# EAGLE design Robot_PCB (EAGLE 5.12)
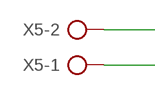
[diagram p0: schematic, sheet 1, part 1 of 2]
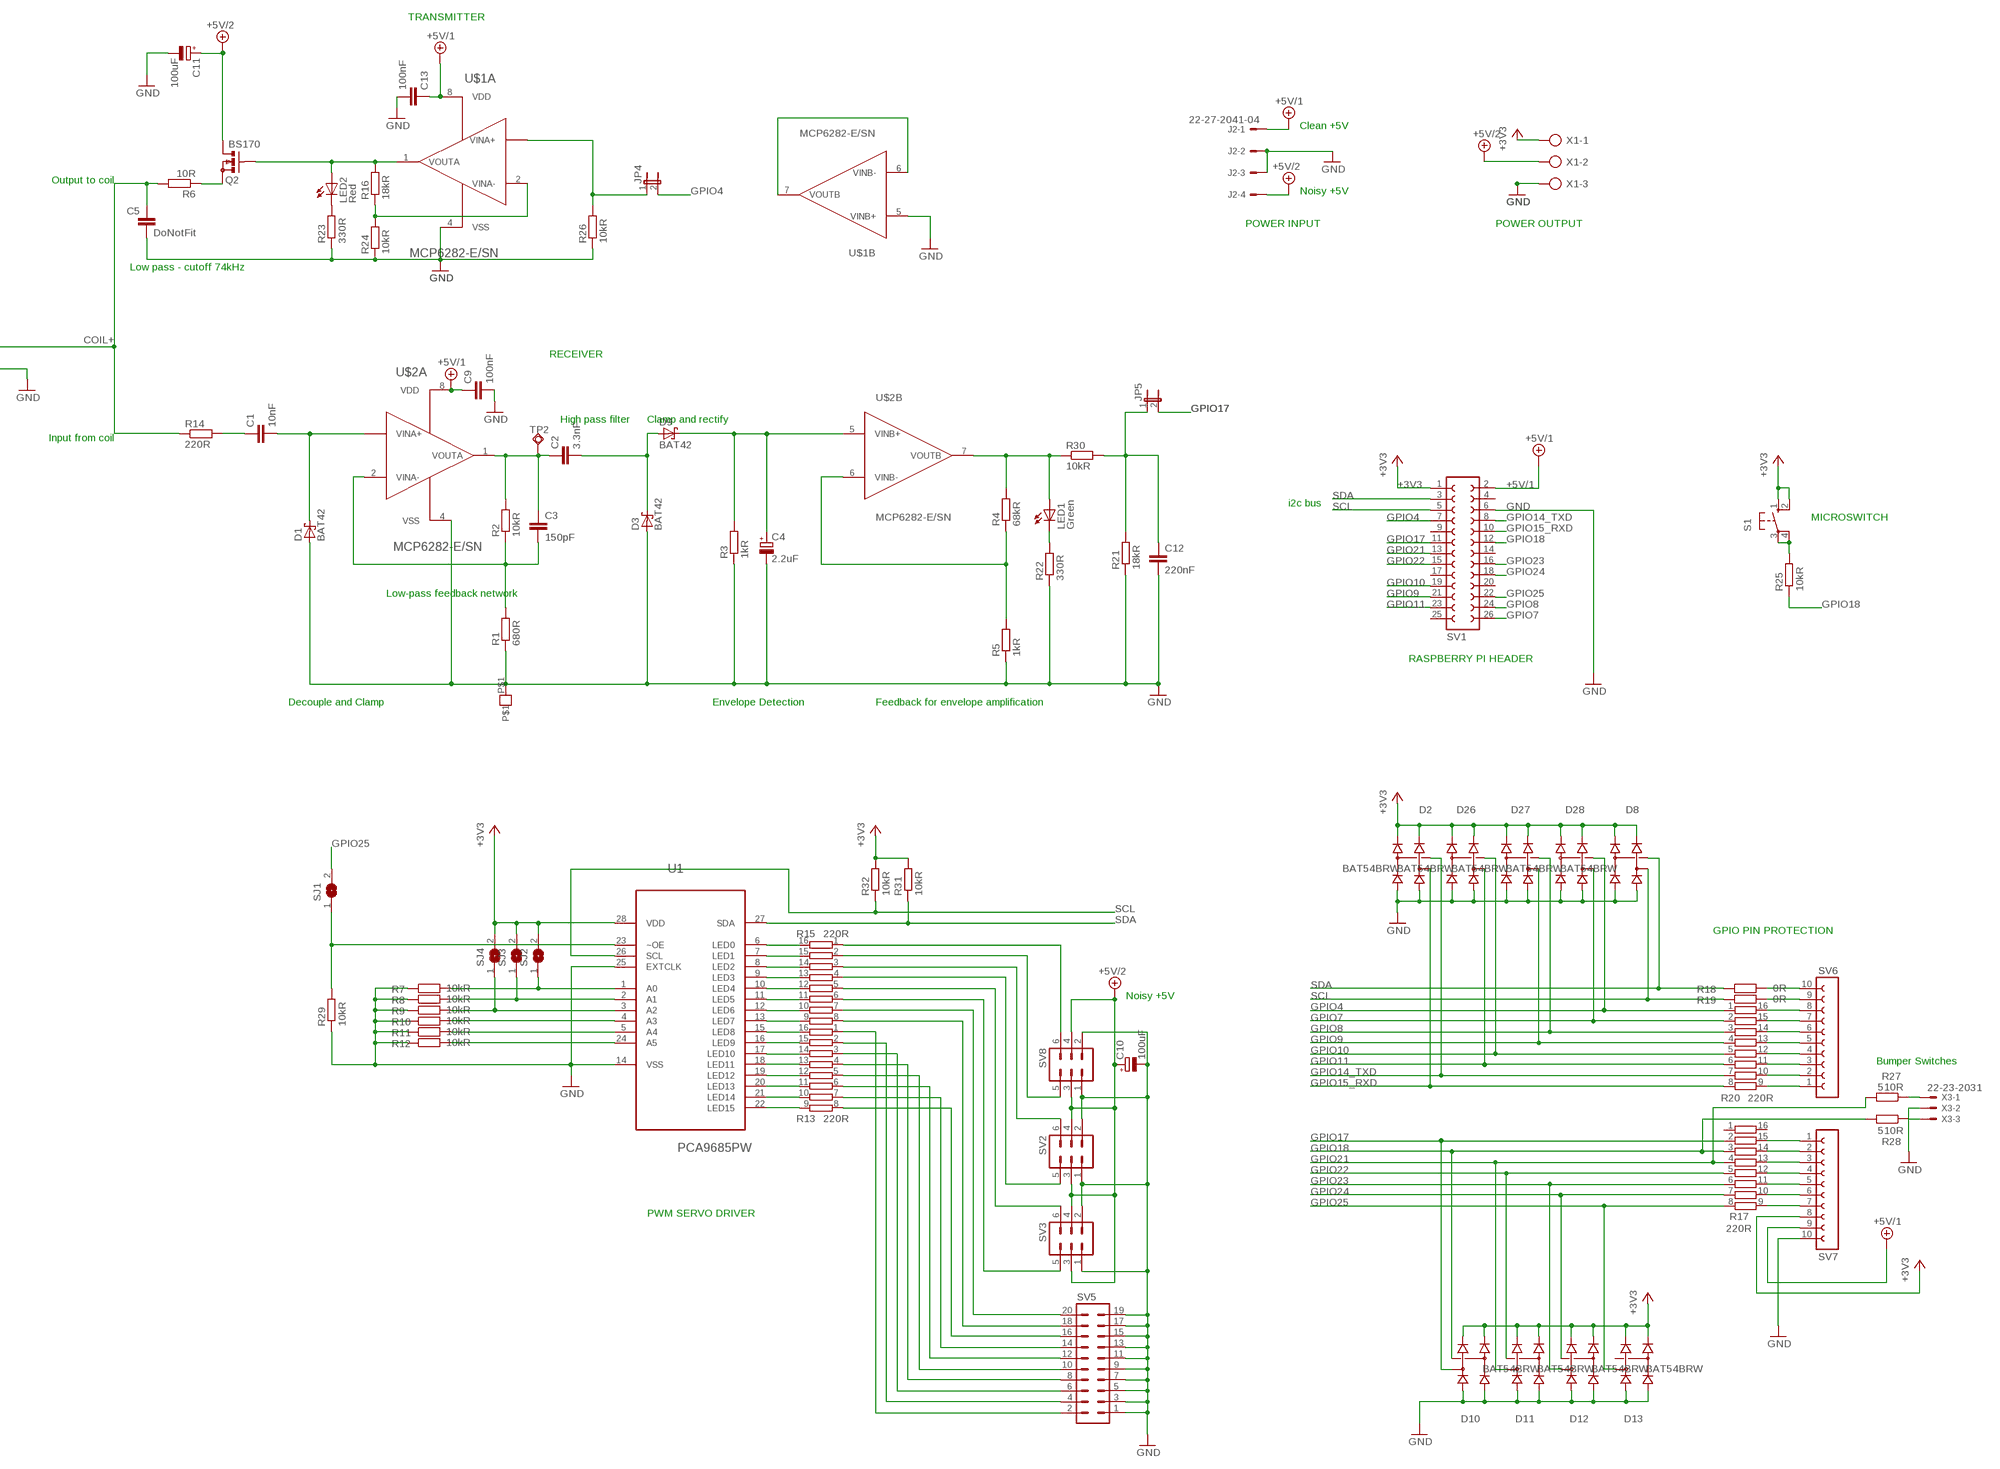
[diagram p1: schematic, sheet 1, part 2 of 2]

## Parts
C1  10nF  C-EUC0603  [C0603]
C2  3.3nF  C-EUC0603  [C0603]
C3  150pF  C-EUC0603  [C0603]
C4  2.2uF  CPOL-EUE2-5  [E2-5]
C5  DoNotFit  C-EU025-024X044  [C025-024X044]
C9  100nF  C-EUC0603  [C0603]
C10  100uF  CPOL-EUE2.5-6  [E2,5-6]
C11  100uF  CPOL-EUE2.5-6  [E2,5-6]
C12  220nF  C-EU025-024X044  [C025-024X044]
C13  100nF  C-EUC0603  [C0603]
D1  BAT42  [DO35-10]
D2  BAT54BRW  [SOT363]
D3  BAT42  [DO35-10]
D8  BAT54BRW  [SOT363]
D9  BAT42  [DO35-10]
D10  BAT54BRW  [SOT363]
D11  BAT54BRW  [SOT363]
D12  BAT54BRW  [SOT363]
D13  BAT54BRW  [SOT363]
D26  BAT54BRW  [SOT363]
D27  BAT54BRW  [SOT363]
D28  BAT54BRW  [SOT363]
J2  22-27-2041-04  [6410-04]
J5  TP  [TP_SMALL]
JP4  JP1E  [JP1]
JP5  JP1E  [JP1]
LED1  Green  LEDSML0805  [SML0805]
LED2  Red  LEDSML0805  [SML0805]
Q2  BS170  [SOT54E]
R1  680R  R-EU_R0603  [R0603]
R2  10kR  R-EU_R0603  [R0603]
R3  1kR  R-EU_R0603  [R0603]
R4  68kR  R-EU_R0603  [R0603]
R5  1kR  R-EU_R0603  [R0603]
R6  10R  R-EU_0207/10  [0207/10]
R7  10kR  R-EU_R0603  [R0603]
R8  10kR  R-EU_R0603  [R0603]
R9  10kR  R-EU_R0603  [R0603]
R10  10kR  R-EU_R0603  [R0603]
R11  10kR  R-EU_R0603  [R0603]
R12  10kR  R-EU_R0603  [R0603]
R13  220R  2NBS16-8  [SO16]
R14  220R  R-EU_R0603  [R0603]
R15  220R  2NBS16-8  [SO16]
R16  18kR  R-EU_R0603  [R0603]
R17  220R  4816P-T01  [4816P]
R18  0R  R-EU_R0603  [R0603]
R19  0R  R-EU_R0603  [R0603]
R20  220R  4816P-T01  [4816P]
R21  18kR  R-EU_R0603  [R0603]
R22  330R  R-EU_R0603  [R0603]
R23  330R  R-EU_R0603  [R0603]
R24  10kR  R-EU_R0603  [R0603]
R25  10kR  R-EU_R0603  [R0603]
R26  10kR  R-EU_R0603  [R0603]
R27  510R  R-EU_R0603  [R0603]
R28  510R  R-EU_R0603  [R0603]
R29  10kR  R-EU_R0603  [R0603]
R30  10kR  R-EU_R0603  [R0603]
R31  10kR  R-EU_R0603  [R0603]
R32  10kR  R-EU_R0603  [R0603]
S1  10-XX  [B3F-10XX]
SJ1  SJ  [SJ]
SJ2  SJ  [SJ]
SJ3  SJ  [SJ]
SJ4  SJ  [SJ]
SV1  FE13-2  [FE13-2]
SV2  MA03-2  [MA03-2]
SV3  MA03-2  [MA03-2]
SV5  MA10-2  [MA10-2]
SV6  FE10-1  [FE10]
SV7  FE10-1  [FE10]
SV8  MA03-2  [MA03-2]
TP2  TPSQTP16SQ  [TP16SQ]
U1  PCA9685PW  [SOP65P640X110-28N]
U$1  MCP6282-E/SN  [SOIC127P600X175-8N]
U$2  MCP6282-E/SN  [SOIC127P600X175-8N]
X1  AK500/3  [AK500/3]
X3  22-23-2031  [22-23-2031]
X5  AK500/2  [AK500/2]

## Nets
+3V3: D2.P$4(C2) D2.P$5(C1) D8.P$4(C2) D8.P$5(C1) D10.P$4(C2) D10.P$5(C1) D11.P$4(C2) D11.P$5(C1) D12.P$4(C2) D12.P$5(C1) D13.P$4(C2) D13.P$5(C1) D26.P$4(C2) D26.P$5(C1) D27.P$4(C2) D27.P$5(C1) D28.P$4(C2) D28.P$5(C1) R31.2 R32.2 S1.1(S) S1.2(S1) SJ2.2 SJ3.2 SJ4.2 SV1.1 SV7.8 U1.28(VDD) X1.1
+5V/1: C9.1 C13.1 J2.1 SV1.2 SV7.9 U$1.8(A:VDD) U$2.8(A:VDD)
+5V/2: C10.+ C11.+ J2.4 Q2.D SV2.3 SV2.4 SV3.3 SV3.4 SV8.3 SV8.4 X1.2
COIL+: C5.1 R6.2 R14.1 X5.2
GND: C4.- C5.2 C9.2 C10.- C11.- C12.2 C13.2 D1.A D2.P$1(A1) D2.P$2(A2) D3.A D8.P$1(A1) D8.P$2(A2) D10.P$1(A1) D10.P$2(A2) D11.P$1(A1) D11.P$2(A2) D12.P$1(A1) D12.P$2(A2) D13.P$1(A1) D13.P$2(A2) D26.P$1(A1) D26.P$2(A2) D27.P$1(A1) D27.P$2(A2) D28.P$1(A1) D28.P$2(A2) J2.2 J2.3 J5.P$1 R1.1 R3.1 R5.1 R7.1 R8.1 R9.1 R10.1 R11.1 R12.1 R21.1 R22.1 R23.1 R24.1 R26.1 R29.1 SV1.6 SV2.1 SV2.2 SV3.1 SV3.2 SV5.1 SV5.3 SV5.5 SV5.7 SV5.9 SV5.11 SV5.13 SV5.15 SV5.17 SV5.19 SV7.10 SV8.1 SV8.2 U1.14(VSS) U1.25(EXTCLK) U$1.4(A:VSS) U$1.5(B:VINB+) U$2.4(A:VSS) X1.3 X3.2 X5.1
GPIO4: D28.P$3(AC2) JP4.2 R20.1 SV1.7
GPIO7: D28.P$6(AC1) R20.2 SV1.26
GPIO8: D27.P$3(AC2) R20.3 SV1.24
GPIO9: D27.P$6(AC1) R20.4 SV1.21
GPIO10: D26.P$3(AC2) R20.5 SV1.19
GPIO11: D26.P$6(AC1) R20.6 SV1.23
GPIO14_TXD: D2.P$3(AC2) R20.7 SV1.8
GPIO15_RXD: D2.P$6(AC1) R20.8 SV1.10
GPIO17: D10.P$6(AC1) JP5.2 R17.2 SV1.11
GPIO18: D10.P$3(AC2) R17.3 R25.1 R28.2 SV1.12
GPIO21: D11.P$6(AC1) R17.4 R27.2 SV1.13
GPIO22: D11.P$3(AC2) R17.5 SV1.15
GPIO23: D12.P$6(AC1) R17.6 SV1.16
GPIO24: D12.P$3(AC2) R17.7 SV1.18
GPIO25: D13.P$6(AC1) R17.8 SJ1.2 SV1.22
N$1: R17.9 SV7.7
N$2: C1.2 D1.C U$2.3(A:VINA+)
N$3: Q2.S R6.1
N$5: C2.1 C3.1 R2.2 TP2.TP U$2.1(A:VOUTA)
N$6: LED1.C R22.2
N$7: C4.+ D9.C R3.2 U$2.5(B:VINB+)
N$8: R7.2 SJ2.1 U1.1(A0)
N$9: R4.1 R5.2 U$2.6(B:VINB-)
N$12: C3.2 R1.2 R2.1 U$2.2(A:VINA-)
N$13: R18.2 SV6.10
N$15: R19.2 SV6.9
N$16: R8.2 SJ3.1 U1.2(A1)
N$21: R15.16 U1.6(LED0)
N$22: R17.10 SV7.6
N$23: R9.2 SJ4.1 U1.3(A2)
N$24: R10.2 U1.4(A3)
N$25: R11.2 U1.5(A4)
N$26: R12.2 U1.24(A5)
N$29: R15.2 SV8.5
N$30: R15.1 SV8.6
N$31: C2.2 D3.C D9.A
N$32: R15.4 SV2.5
N$33: R15.5 SV3.6
N$34: R15.6 SV3.5
N$35: R15.15 U1.7(LED1)
N$36: R15.14 U1.8(LED2)
N$38: R15.13 U1.9(LED3)
N$39: R15.12 U1.10(LED4)
N$40: R15.11 U1.11(LED5)
N$41: R15.10 U1.12(LED6)
N$42: R15.9 U1.13(LED7)
N$43: R13.16 U1.15(LED8)
N$44: R13.15 U1.16(LED9)
N$45: R13.14 U1.17(LED10)
N$46: R13.13 U1.18(LED11)
N$47: R13.12 U1.19(LED12)
N$48: R13.11 U1.20(LED13)
N$49: R13.10 U1.21(LED14)
N$50: R13.9 U1.22(LED15)
N$51: R15.7 SV5.20
N$52: R15.8 SV5.18
N$53: R13.8 SV5.16
N$54: R13.7 SV5.14
N$55: R13.6 SV5.12
N$56: R13.5 SV5.10
N$57: R13.4 SV5.8
N$58: R13.3 SV5.6
N$59: R13.2 SV5.4
N$60: R13.1 SV5.2
N$61: C1.1 R14.2
N$62: JP4.1 R26.2 U$1.3(A:VINA+)
N$63: LED1.A R4.2 R30.1 U$2.7(B:VOUTB)
N$64: R17.11 SV7.5
N$65: R17.12 SV7.4
N$71: R17.13 SV7.3
N$72: R17.14 SV7.2
N$73: R17.15 SV7.1
N$75: LED2.A Q2.G R16.2 U$1.1(A:VOUTA)
N$78: R20.9 SV6.1
N$79: R16.1 R24.2 U$1.2(A:VINA-)
N$80: C12.1 JP5.1 R21.2 R30.2
N$82: R15.3 SV2.6
N$83: R20.10 SV6.2
N$85: R28.1 X3.3
N$92: R20.11 SV6.3
N$93: R20.12 SV6.4
N$94: R20.13 SV6.5
N$95: R20.14 SV6.6
N$96: R20.15 SV6.7
N$97: R20.16 SV6.8
N$98: R25.2 S1.3(P) S1.4(P1)
N$105: LED2.C R23.2
N$132: R27.1 X3.1
N$133: U$1.6(B:VINB-) U$1.7(B:VOUTB)
SCL: D8.P$6(AC1) R19.1 R32.1 SV1.5 U1.26(SCL)
SDA: D8.P$3(AC2) R18.1 R31.1 SV1.3 U1.27(SDA)
~ENAB_PCA9685PW: R29.2 SJ1.1 U1.23(~OE)
Unconnected: D13.P$3(AC2) R17.1 R17.16 SV1.4 SV1.9 SV1.14 SV1.17 SV1.20 SV1.25

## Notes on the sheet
- TRANSMITTER
- Clean +5V
- Output to coil
- Noisy +5V
- POWER INPUT | POWER OUTPUT
- Low pass - cutoff 74kHz
- RECEIVER
- High pass filter | Clamp and rectify
- Input from coil
- i2c bus
- MICROSWITCH
- Low-pass feedback network
- RASPBERRY PI HEADER
- Decouple and Clamp | Envelope Detection | Feedback for envelope amplification
- GPIO PIN PROTECTION
- Noisy +5V
- Bumper Switches
- PWM SERVO DRIVER

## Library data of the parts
C1-C3 C5 C9 C12 C13 = resistor:C-EU: CAPACITOR, European symbol
C4 C10 C11 = resistor:CPOL-EU: POLARIZED CAPACITOR, European symbol
D1 D3 D9 = diode:BAT42: DIODE
D2 D8 D10-D13 D26-D28 = dtg:BAT54BRW
J2 = con-molex:22-?-04: CONNECTOR wire to board 2.54 mm (.1 inch) pitch header; OC_FARNELL: unknown; OC_NEWARK: unknown
J5 = dtg:TP
JP4 JP5 = jumper:JP1E: JUMPER
LED1 LED2 = led:LED: LED
Q2 = transistor-small-signal:BS170: N-CHANNEL MOS FET
R1-R12 R14 R16 R18 R19 R21-R32 = resistor:R-EU_: RESISTOR, European symbol
R13 R15 = resistor-bourns:2NBS16-8: BOURNS RESISTOR NETWORK; OC_FARNELL: unknown; OC_NEWARK: unknown
R17 R20 = resistor-bourns:4816P-T01: BOURNS RESISTOR NETWORK; MF: BOURNS, INC.; MPN: 4816P-T01-684LF; OC_FARNELL: 9357483; OC_NEWARK: 33K0707
S1 = switch-omron:10-XX: OMRON SWITCH; MPN: B3F-1000; OC_FARNELL: 176432; OC_NEWARK: 36M3542
SJ1-SJ4 = jumper:SJ: SMD solder JUMPER
SV1 = con-lsta:FE13-2: FEMALE HEADER; OC_FARNELL: unknown; OC_NEWARK: unknown
SV2 SV3 SV8 = con-lstb:MA03-2: PIN HEADER; OC_FARNELL: unknown; OC_NEWARK: unknown
SV5 = con-lstb:MA10-2: PIN HEADER; OC_FARNELL: unknown; OC_NEWARK: unknown
SV6 SV7 = con-lsta:FE10-1: FEMALE HEADER; OC_FARNELL: unknown; OC_NEWARK: unknown
TP2 = testpad:TPSQ: Test pad
U1 = NXP_PCA9685PW:PCA9685PW: 16-channel, 12-bit PWM Fm+ I2C-bus LED controller; MPN: PCA9685PW; OC_FARNELL: 1854074; OC_NEWARK: 19T6398; PACKAGE: TSSOP-28; SUPPLIER: NXP
U$1 U$2 = MCP6282_mine:MCP6282-E/SN: Rail-to-Rail Op Amp; DESCRIPTION: OP AMP; MPN: MCP6282-E/SN; OC_FARNELL: 1439459; OC_NEWARK: 58M8972; PACKAGE: SOIC-8; SUPPLIER: Microchip
X1 = con-ptr500:AK500/3: CONNECTOR; OC_FARNELL: unknown; OC_NEWARK: unknown
X3 = con-molex:22-23-2031: .100" (2.54mm) Center Header - 3 Pin; MF: MOLEX; MPN: 22-23-2031; OC_FARNELL: 1462950; OC_NEWARK: 30C0862
X5 = con-ptr500:AK500/2: CONNECTOR; OC_FARNELL: unknown; OC_NEWARK: unknown

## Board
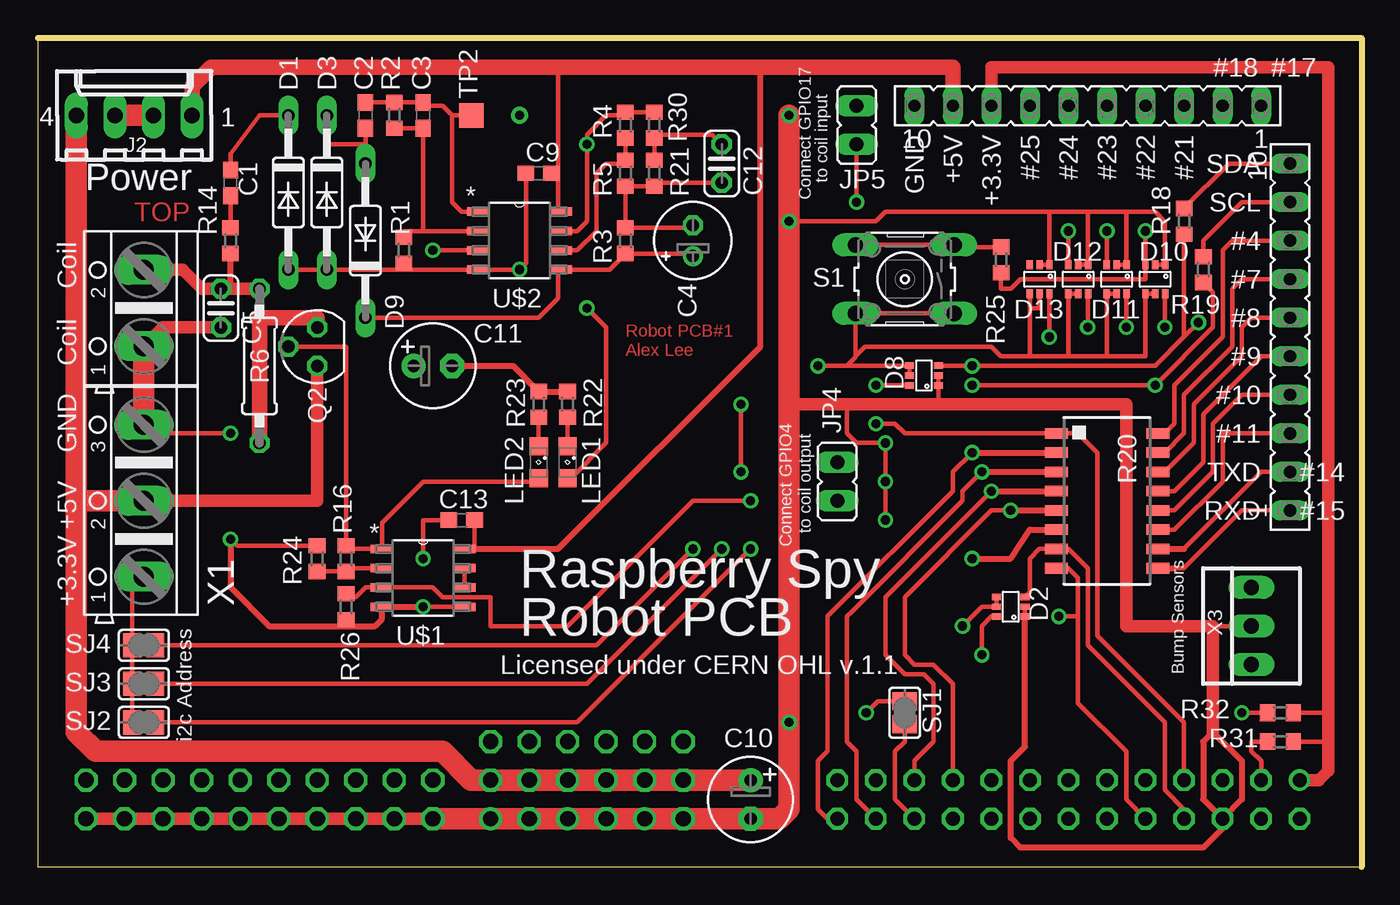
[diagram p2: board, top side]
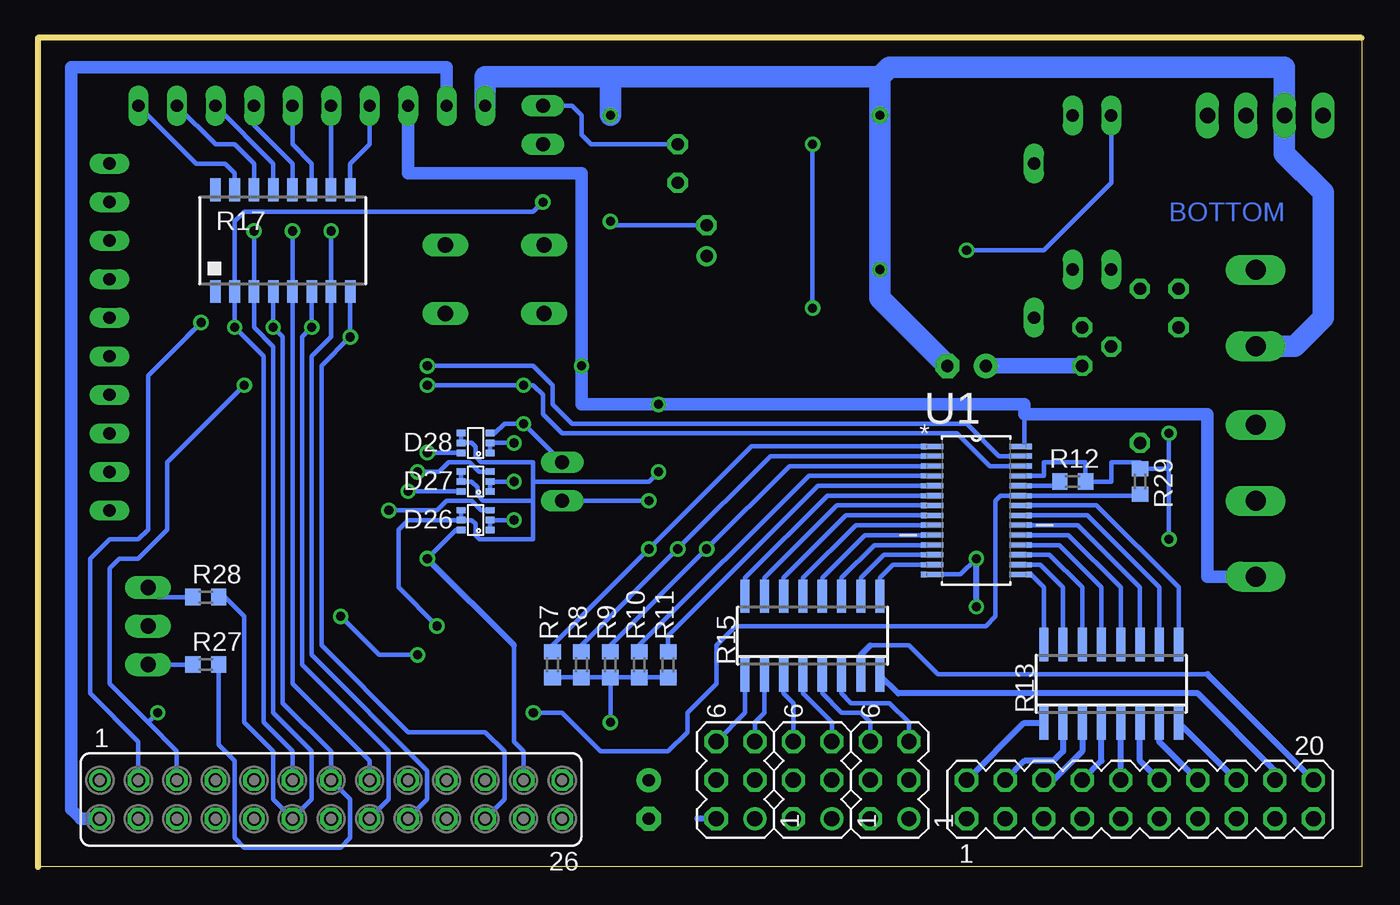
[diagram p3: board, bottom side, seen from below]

Size 87.27 x 54.63 mm. Coordinates in mm from the lower left corner, seen from the top.
Outline: 0,0 87.27,0 87.27,54.63 0,54.63 0,0
Copper layers (1*16): Top 0.035mm / dielectric 1.5mm / Bottom 0.035mm
Design rules "default *": minimum track width 10mil, minimum drill 23mil, track to track 8mil, track to pad 8mil, pad to pad 8mil, via to via 8mil, smd to smd 8mil, copper to edge 40mil, drill to drill 8mil, minimum pad ring 10mil, minimum via ring 8mil, stop-mask expansion 4mil, vias tented up to drill 0mil, thermal gap 15mil

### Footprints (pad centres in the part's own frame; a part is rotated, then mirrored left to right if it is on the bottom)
C0603 = smd 1.1 x 1: 1 -0.85,0; 2 0.85,0
E2-5 = drill 0.813 pad 1.27 round: + -1.016,0 | drill 0.813 pad 1.27 octagon: - 1.016,0
C025-024X044 = drill 0.813 octagon: 1 -1.27,0; 2 1.27,0
E2,5-6 = drill 0.813 pad 1.6 round: + -1.27,0 | drill 0.813 pad 1.6 octagon: - 1.27,0
DO35-10 = drill 0.813 long: A 5.08,0; C -5.08,0
SOT363 = smd 0.42 x 0.6: P$1 -0.65,-0.95; P$2 0,-0.95; P$3 0.65,-0.95; P$4 0.65,0.95; P$5 0,0.95; P$6 -0.65,0.95
6410-04 = drill 1.016 long: 1 3.81,0; 2 1.27,0; 3 -1.27,0; 4 -3.81,0
TP_SMALL = drill 0.6 pad 0.813 round: P$1 0,0
JP1 = drill 0.914 long: 1 0,-1.27; 2 0,1.27
SML0805 = smd 1.2 x 1.2: A 1.05,0; C -1.05,0
SOT54E = drill 0.813 octagon: D -1.27,0; G 0,1.905; S 1.27,0
R0603 = smd 1 x 1.1: 1 -0.85,0; 2 0.85,0
0207/10 = drill 0.813 octagon: 1 -5.08,0; 2 5.08,0
SO16 = smd 0.6 x 2.2: 1 -4.445,-2.6; 2 -3.175,-2.6; 3 -1.905,-2.6; 4 -0.635,-2.6; 5 0.635,-2.6; 6 1.905,-2.6; 7 3.175,-2.6; 8 4.445,-2.6; 9 4.445,2.6; 10 3.175,2.6; 11 1.905,2.6; 12 0.635,2.6; 13 -0.635,2.6; 14 -1.905,2.6; 15 -3.175,2.6; 16 -4.445,2.6
4816P = smd 0.7 x 1.5: 1 -4.445,-3.346; 2 -3.175,-3.346; 3 -1.905,-3.346; 4 -0.635,-3.346; 5 0.635,-3.346; 6 1.905,-3.346; 7 3.175,-3.346; 8 4.445,-3.346; 9 4.445,3.346; 10 3.175,3.346; 11 1.905,3.346; 12 0.635,3.346; 13 -0.635,3.346; 14 -1.905,3.346; 15 -3.175,3.346; 16 -4.445,3.346
B3F-10XX = drill 1.016 long: 1 -3.251,2.261; 2 3.251,2.261; 3 -3.251,-2.261; 4 3.251,-2.261
SJ = smd 1.168 x 1.6: 1 -0.762,0; 2 0.762,0
FE13-2 = drill 0.914 round: 1 -15.24,1.27 | drill 0.914 octagon: 2 -15.24,-1.27; 3 -12.7,1.27; 4 -12.7,-1.27; 5 -10.16,1.27; 6 -10.16,-1.27; 7 -7.62,1.27; 8 -7.62,-1.27; 9 -5.08,1.27; 10 -5.08,-1.27; 11 -2.54,1.27; 12 -2.54,-1.27; 13 0,1.27; 14 0,-1.27; 15 2.54,1.27; 16 2.54,-1.27; 17 5.08,1.27; 18 5.08,-1.27; 19 7.62,1.27; 20 7.62,-1.27; 21 10.16,1.27; 22 10.16,-1.27; 23 12.7,1.27; 24 12.7,-1.27; 25 15.24,1.27; 26 15.24,-1.27
MA03-2 = drill 1.016 round: 1 -2.54,-1.27 | drill 1.016 octagon: 2 -2.54,1.27; 3 0,-1.27; 4 0,1.27; 5 2.54,-1.27; 6 2.54,1.27
MA10-2 = drill 1.016 octagon: 1 -11.43,-1.27; 2 -11.43,1.27; 3 -8.89,-1.27; 4 -8.89,1.27; 5 -6.35,-1.27; 6 -6.35,1.27; 7 -3.81,-1.27; 8 -3.81,1.27; 9 -1.27,-1.27; 10 -1.27,1.27; 11 1.27,-1.27; 12 1.27,1.27; 13 3.81,-1.27; 14 3.81,1.27; 15 6.35,-1.27; 16 6.35,1.27; 17 8.89,-1.27; 18 8.89,1.27; 19 11.43,-1.27; 20 11.43,1.27
FE10 = drill 0.813 long: 1 -11.43,0; 2 -8.89,0; 3 -6.35,0; 4 -3.81,0; 5 -1.27,0; 6 1.27,0; 7 3.81,0; 8 6.35,0; 9 8.89,0; 10 11.43,0
TP16SQ = smd 1.6 x 1.6: TP 0,0
SOP65P640X110-28N = smd 1.473 x 0.356: 1 -2.921,4.216; 2 -2.921,3.581; 3 -2.921,2.921; 4 -2.921,2.286; 5 -2.921,1.626; 6 -2.921,0.965; 7 -2.921,0.33; 8 -2.921,-0.33; 9 -2.921,-0.965; 10 -2.921,-1.626; 11 -2.921,-2.286; 12 -2.921,-2.921; 13 -2.921,-3.581; 14 -2.921,-4.216; 15 2.921,-4.216; 16 2.921,-3.581; 17 2.921,-2.921; 18 2.921,-2.286; 19 2.921,-1.626; 20 2.921,-0.965; 21 2.921,-0.33; 22 2.921,0.33; 23 2.921,0.965; 24 2.921,1.626; 25 2.921,2.286; 26 2.921,2.921; 27 2.921,3.581; 28 2.921,4.216
SOIC127P600X175-8N = smd 1.473 x 0.559: 1 -2.718,1.905; 2 -2.718,0.635; 3 -2.718,-0.635; 4 -2.718,-1.905; 5 2.718,-1.905; 6 2.718,-0.635; 7 2.718,0.635; 8 2.718,1.905
AK500/3 = drill 1.321 long: 1 -5.004,0; 2 0,0; 3 5.004,0
22-23-2031 = drill 1 long: 1 -2.54,0; 2 0,0; 3 2.54,0
AK500/2 = drill 1.321 long: 1 -2.515,0; 2 2.515,0

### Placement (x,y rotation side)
C1  12.7,45.09 90 top
C2  21.59,49.53 270 top
C3  25.4,49.53 270 top
C4  43.18,41.27 90 top
C5  12.06,36.83 270 top
C9  33.02,45.72 180 top
C10  46.99,4.45 270 top
C11  26.04,33.02 0 top
C12  45.09,46.35 270 top
C13  27.94,22.86 180 top
D1  16.51,44.45 270 top
D2  64.14,17.14 90 top
D3  19.05,44.45 270 top
D8  58.42,32.38 90 top
D9  21.59,41.27 90 top
D10  73.66,38.73 180 top
D11  71.12,38.73 180 top
D12  68.58,38.73 180 top
D13  66.04,38.73 180 top
D26  58.42,22.86 90 bottom
D27  58.42,25.4 90 bottom
D28  58.42,27.94 90 bottom
J2  6.35,49.53 0 top
J5  31.75,49.53 0 top
JP4  52.7,25.4 0 top
JP5  53.98,48.9 180 top
LED1  34.92,26.67 270 top
LED2  33.02,26.67 270 top
Q2  18.41,34.29 90 top
R1  24.13,40.64 90 top
R2  23.5,49.53 90 top
R3  38.73,41.27 270 top
R4  38.73,48.9 90 top
R5  38.73,45.72 90 top
R6  14.61,33.02 90 top
R7  53.34,13.34 90 bottom
R8  51.44,13.34 90 bottom
R9  49.53,13.34 90 bottom
R10  47.62,13.34 90 bottom
R11  45.72,13.34 90 bottom
R12  19.05,25.4 180 bottom
R13  16.51,12.06 0 bottom
R14  12.7,41.27 90 top
R15  36.2,15.24 0 bottom
R16  20.32,20.32 90 top
R17  71.12,41.27 0 bottom
R18  75.56,42.55 90 top
R19  76.83,39.37 90 top
R20  70.48,24.13 270 top
R21  40.64,45.72 90 top
R22  34.92,30.48 270 top
R23  33.02,30.48 270 top
R24  18.41,20.32 270 top
R25  63.5,40.01 90 top
R26  20.32,17.14 90 top
R27  76.2,13.34 0 bottom
R28  76.2,17.78 0 bottom
R29  14.61,25.4 270 bottom
R30  40.64,48.9 270 top
R31  81.92,8.26 0 top
R32  81.92,10.16 0 top
S1  57.15,38.73 180 top
SJ1  57.15,10.16 270 top
SJ2  6.99,9.53 180 top
SJ3  6.99,12.06 180 top
SJ4  6.99,14.61 180 top
SV1  67.94,4.45 0 bottom
SV2  36.2,5.71 90 bottom
SV3  31.11,5.71 90 bottom
SV5  14.61,4.45 0 bottom
SV6  82.55,34.92 90 top
SV7  69.22,50.16 180 top
SV8  41.27,5.71 90 bottom
TP2  28.57,49.53 0 top
U1  25.4,23.5 0 bottom
U$1  25.4,19.05 0 top
U$2  31.75,41.27 0 top
X1  6.99,24.13 90 top
X3  80.01,15.88 90 top
X5  6.99,36.83 90 top

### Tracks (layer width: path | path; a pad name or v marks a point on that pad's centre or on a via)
+3V3  (via drill 0.6)
  Top 0.305: SJ2.2 SJ3.2 SJ4.2 6.22,19 6.1,19.13 X1.1 | S1.1 S1.2 53.9,33.66 | 53.9,33.66 53.9,33.58 53.35,33.03 | v51.44,33.02 53.34,33.02 53.35,33.03 | 67.94,33.66 67.93,33.67 D12.P$4 D12.P$5 | 65.41,33.66 63.5,33.66 62.87,34.29 54.53,34.29 53.9,33.66 | 65.41,33.66 67.94,33.66 | 65.39,36.83 65.39,33.67 65.41,33.66 | 65.39,36.83 D13.P$4 | 70.48,33.66 70.47,33.67 D11.P$4 D11.P$5 | 67.94,33.66 70.48,33.66 | 70.48,33.66 73.03,33.66 73.01,33.67 D10.P$4 D10.P$5 | D8.P$5 D8.P$4 53.35,33.03 | v46.35,30.48 v46.35,26.04 | v60.96,15.88 62.23,17.14 D2.P$5 D2.P$4 | D13.P$5 66.04,36.83 65.39,36.83 | 85.09,8.26 R31.2 | 85.09,10.16 R32.2
  Top 0.813: SV7.8 62.87,52.7 85.09,52.7 85.09,10.16 85.09,8.26 85.09,6.35 84.45,5.71 SV1.1
  Bottom 0.305: U1.28 22.23,27.71 22.23,29.84 | D27.P$4 D27.P$5 58.67,25.4 58.29,25.02 58.29,24.51 57.91,24.13 54.61,24.13 | D28.P$5 59.05,27.94 | D26.P$5 D26.P$4 59.37,23.18 | D28.P$5 D28.P$4 | 54.61,24.13 54.61,21.59 58.17,21.59 58.42,21.84 58.42,22.61 58.67,22.86 D26.P$5 | 54.61,25.4 54.61,24.13 | 54.61,25.4 54.61,26.67 58.04,26.67 58.42,27.05 58.42,27.69 58.67,27.94 D28.P$5 | v46.35,26.04 46.99,25.4 54.61,25.4 | v60.96,15.88 63.5,18.41 63.5,22.23 62.87,22.86 D26.P$5
  Bottom 0.813: X1.1 10.16,19.13 10.16,29.84 22.23,29.84 22.23,30.48 v46.35,30.48 51.44,30.48 v51.44,33.02 51.44,45.72 62.87,45.72 SV7.8
+5V/1
  Top 0.305: U$2.8 34.29,43.18 34.29,45.72 | 34.29,52.7 34.29,45.72 | 34.29,45.72 C9.1 | C13.1 28.79,21.17 28.57,20.95
  Top 0.406: U$1.8 28.57,20.95 34.29,20.95 47.62,34.29 47.62,52.7
  Top 1.016: SV7.9 60.33,52.7 47.62,52.7 34.29,52.7 11.43,52.7 10.16,51.44 J2.1
  Bottom 0.813: SV7.9 60.33,52.7 85.09,52.7 85.09,3.81 84.45,3.17 SV1.2
+5V/2
  Top 0.813: X1.2 18.41,24.13 Q2.D
  Top 1.422: 2.54,24.13 X1.2 | 2.54,24.13 2.54,8.89 3.81,7.62 26.67,7.62 28.57,5.71 SV3.3 SV3.4 SV2.3 SV2.4 SV8.3 SV8.4 C10.+ | 2.54,24.13 J2.4
  Bottom 1.016: Q2.D C11.+
COIL+
  Top 0.406: 12.7,38.1 R14.1
  Top 0.813: R6.2 14.82,38.1 | R6.2 14.39,37.88 | X5.2 9.55,39.34 10.79,38.1 C5.1 12.7,38.1 R6.2
GND  (via drill 0.6)
  Top 0.305: D1.A D3.A 24.13,39.37 | 24.13,39.37 R1.1 | 24.13,39.37 U$2.4 v31.75,39.37 32.17,39.79 C9.2 | C12.2 40.85,45.09 R21.1 R5.1 R3.1 43.01,42.12 C4.- | 49.53,34.29 49.15,34.67 | v12.7,28.57 5.71,28.57 X1.3 | 49.53,27.3 49.53,27.52 | R24.1 13.12,21.17 v12.7,21.59 | C13.2 25.4,22.86 v25.4,20.32 | 77.47,15.88 X3.2 | 66.67,43.18 55.88,43.18 55.24,42.55 v49.53,42.55 | 66.67,43.18 69.22,43.18 | 69.22,43.18 71.75,43.18 | 71.75,43.18 73.66,43.18 74.31,42.53 D10.P$1 D10.P$2 | 71.75,43.18 71.77,43.16 D11.P$1 D11.P$2 | 69.22,43.18 69.23,43.16 D12.P$1 D12.P$2 | 66.67,43.18 66.69,43.16 D13.P$1 D13.P$2 | 59.69,30.48 59.37,30.8 D8.P$1 D8.P$2 | v55.88,22.86 v55.88,25.4 v55.88,27.94 53.98,27.94 53.34,28.57 53.34,30.48 | D2.P$1 D2.P$2 | v25.4,17.14 U$1.5
  Top 0.406: v12.7,21.59 12.7,18.41 15.24,15.88 20.32,15.88 | 20.32,15.88 22.23,15.88 22.68,16.33 U$1.4 v25.4,17.14 | 20.32,15.88 R26.1 | C11.- 31.33,33.02 R23.1 R22.1 | SV1.6 76.83,4.45 76.83,8.26 77.47,8.89 79.38,6.99 79.38,4.45 SV1.6 | D2.P$1 65.08,7.93 64.14,6.99 64.14,1.91 64.77,1.27 76.83,1.27 78.11,2.54 SV1.6
  Top 0.813: 49.53,30.48 53.34,30.48 59.69,30.48 71.75,30.48 71.75,15.88 77.47,15.88 77.47,8.89 | SV5.1 SV5.3 SV5.5 SV5.7 SV5.9 | SV5.9 15.24,3.17 | SV5.9 SV5.11 SV5.13 SV5.15 SV5.17 SV5.19 | C5.2 8.23,35.56 X5.1
  Top 1.422: J2.3 J2.2 | v49.53,49.53 v49.53,42.55 49.53,34.29 49.53,30.48 49.53,27.3 v49.53,9.53 49.53,3.81 48.9,3.17 C10.- SV8.2 SV8.1 SV2.2 SV2.1 SV3.2 SV3.1 SV5.1 | X5.1 X1.3
  Bottom 0.305: R9.1 R8.1 R7.1 | R9.1 R10.1 R11.1 | U1.25 20.95,25.78 20.95,26.67 18.2,26.67 R12.1 16.51,25.4 16.51,26.67 14.61,26.67 R29.1 12.7,26.25 | v12.7,28.57 12.7,26.25 | v49.53,9.53 R9.1 | 12.7,26.25 v12.7,21.59 | C4.- 49.28,42.29 v49.53,42.55 | D26.P$1 D26.P$2 v55.88,22.86 | D27.P$1 D27.P$2 v55.88,25.4 | D28.P$1 D28.P$2 v55.88,27.94 | U1.14 26.44,19.28 v25.4,20.32
  Bottom 0.406: SV8.2 43.81,3.17 | v25.4,17.14 v25.4,20.32
  Bottom 1.422: 49.53,52.07 31.75,52.07 | 49.53,52.07 57.78,52.07 SV7.10 | 31.75,52.07 J5.P$1 v31.75,39.37 31.75,37.47 C11.- | v49.53,49.53 49.53,52.07 | 31.75,52.07 31.11,52.7 5.08,52.7 J2.3 5.08,46.99 2.54,44.45 2.54,36.2 4.42,34.31 X5.1
GPIO4  (via drill 0.6)
  Top 0.305: v55.24,29.21 56.52,29.21 57.15,28.57 R20.1 68.58,28.57 69.85,27.3 69.85,15.24 75.56,9.53 SV1.7
  Bottom 0.305: D28.P$3 57.45,28.57 57.15,28.57 56.52,29.21 v55.24,29.21 JP4.2
GPIO7  (via drill 0.6)
  Top 0.305: v61.59,27.3 60.33,26.04 60.33,24.77 52.07,16.51 52.07,7.62 51.44,6.99 51.44,3.81 52.07,3.17 SV1.26
  Top 0.406: v61.59,27.3 R20.2
  Bottom 0.305: D28.P$6 v61.58,27.29 v61.59,27.3
GPIO8  (via drill 0.6)
  Top 0.305: v62.23,26.04 60.96,24.77 60.96,24.13 53.66,16.83 53.34,16.51 53.34,8.26 53.98,7.62 53.98,4.45 SV1.24
  Top 0.406: v62.23,26.04 R20.3
  Bottom 0.305: D27.P$3 58.18,26.05 58.8,26.67 60.2,26.67 60.83,26.04 v62.23,26.04
GPIO9  (via drill 0.6)
  Top 0.305: v62.87,24.77 55.88,17.78 55.88,13.97 57.15,12.7 58.42,12.7 59.05,12.06 59.05,8.26 57.78,6.99 SV1.21
  Top 0.406: v62.87,24.77 R20.4
  Bottom 0.305: D27.P$6 62.85,24.75 v62.87,24.77
GPIO10  (via drill 0.6)
  Top 0.305: v64.14,23.5 62.87,23.5 57.15,17.78 57.15,13.97 57.78,13.34 59.05,13.34 60.33,12.06 SV1.19
  Top 0.406: v64.14,23.5 R20.5
  Bottom 0.305: D26.P$3 58.05,23.51 58.67,24.13 60.33,24.13 60.96,23.5 v64.14,23.5
GPIO11  (via drill 0.6)
  Top 0.406: v61.59,20.32 64.14,20.32 65.41,22.23 R20.6
  Bottom 0.305: D26.P$6 59.7,22.21 v61.59,20.32 | 55.88,14.61 55.88,8.26 55.24,7.62 SV1.23
  Bottom 0.406: 55.88,14.61 v61.59,20.32
GPIO14_TXD
  Top 0.305: D2.P$3 65.41,18.11 65.41,20.32 66.04,20.95 R20.7 67.94,20.95 69.22,19.68 69.22,14.61 74.3,9.53 74.3,5.08 75.56,3.81 SV1.8
GPIO15_RXD  (via drill 0.6)
  Top 0.305: R20.8 67.94,19.68 68.58,19.05 68.58,16.51 | 68.58,16.51 68.58,10.79 71.75,7.62 71.75,4.45 SV1.10 | D2.P$6 63.48,16.5 63.5,16.51 62.87,16.51 62.23,15.88 v62.23,13.97 | 68.58,16.51 v67.31,16.51
  Bottom 0.305: v62.23,13.97 64.77,13.97 v67.31,16.51
GPIO17  (via drill 0.6)
  Top 0.305: v53.98,43.81 JP5.2 | 74.3,37.47 74.3,37.77 D10.P$6 74.31,37.48 74.3,37.47 | v74.3,35.56 74.3,37.47
  Bottom 0.305: v53.98,43.81 54.61,43.18 73.66,43.18 74.3,42.55 R17.2 v74.3,35.56 72.39,33.66 72.39,9.53 70.48,7.62 SV1.11
GPIO18  (via drill 0.6)
  Top 0.305: v73.03,41.91 73.03,40.97 D10.P$3 73.03,39.67 73.03,38.73 64.77,38.73 64.14,38.1 63.5,38.1 R25.1
  Bottom 0.305: v73.03,41.91 R17.3 73.03,35.56 71.75,34.29 71.75,10.16 69.22,7.62 69.22,4.45 SV1.12 71.75,4.45 71.75,7.62 73.66,9.53 73.66,16.51 74.93,17.78 R28.2
GPIO21  (via drill 0.6)
  Top 0.305: D11.P$6 71.75,37.13 v71.75,35.56
  Bottom 0.305: R17.4 v71.75,35.56 71.12,34.92 71.12,10.79 67.94,7.62 SV1.13 66.67,4.45 66.67,1.91 67.31,1.27 73.66,1.27 74.3,1.91 74.3,6.99 75.35,8.04 R27.2
GPIO22  (via drill 0.6)
  Top 0.305: D11.P$3 70.47,41.9 v70.48,41.91
  Bottom 0.305: v70.48,41.91 R17.5 70.48,12.06 65.41,6.99 SV1.15
GPIO23  (via drill 0.6)
  Top 0.305: v69.22,35.56 69.22,37.13 D12.P$6
  Bottom 0.305: R17.6 v69.22,35.56 69.85,34.92 69.85,13.34 64.14,7.62 64.14,4.45 SV1.16
GPIO24  (via drill 0.6)
  Top 0.305: D12.P$3 67.93,41.9 v67.94,41.91
  Bottom 0.305: v67.94,41.91 R17.7 67.94,34.92 69.22,33.66 69.22,13.97 61.59,6.35 61.59,4.45 SV1.18
GPIO25  (via drill 0.6)
  Top 0.305: v66.67,34.92 66.67,36.5 D13.P$6 | SJ1.2 57.15,8.26 56.52,7.62 56.52,4.45 SV1.22
  Bottom 0.305: R17.8 v66.67,34.92 68.58,33.02 68.58,14.61 62.87,8.89 57.78,8.89 56.52,7.62 56.52,4.45 SV1.22
N$1
  Bottom 0.305: R17.9 66.67,46.35 65.41,47.62 SV7.7
N$2  (via drill 0.6)
  Top 0.305: v26.04,40.64 U$2.3 | C1.2 12.7,46.99 14.61,49.53 D1.C
  Bottom 0.305: v26.04,40.64 20.95,40.64 16.51,45.09 D1.C
N$3
  Top 1.016: R6.1 14.61,36.2 18.41,36.2 Q2.S
N$5
  Top 0.305: C2.1 R2.2 C3.1 25.4,50.16 26.67,50.16 27.3,49.53 | 27.3,49.53 27.3,43.81 27.94,43.18 U$2.1 | 27.3,49.53 TP2.TP
N$6
  Top 0.305: LED1.C R22.2
N$7
  Top 0.305: D9.C 33.02,36.2 34.29,37.47 34.29,39.19 U$2.5 37.68,39.37 R3.2 43.01,40.42 C4.+
N$8  (via drill 0.6)
  Top 0.305: SJ2.1 35.56,9.53 v46.99,20.95
  Bottom 0.305: U1.1 40.23,27.71 v46.99,20.95 53.34,14.61 R7.2
N$9
  Top 0.305: R4.1 R5.2 38.52,46.35 37.47,46.35 36.83,45.72 36.83,41.91 35.56,40.64 U$2.6
N$12
  Top 0.305: 25.4,41.91 C3.2 R2.1 | 25.4,41.91 U$2.2 | R1.2 24.13,41.91 25.4,41.91
N$13
  Top 0.305: SV6.10 78.53,46.35 R18.2
N$15
  Top 0.305: SV6.9 79.38,43.81 76.83,41.27 R19.2
N$16  (via drill 0.6)
  Top 0.305: SJ3.1 36.2,12.06 v45.09,20.95
  Bottom 0.305: U1.2 38.96,27.08 v45.09,20.95 51.44,14.61 R8.2
N$21
  Bottom 0.305: U1.6 35.23,24.46 40.64,19.05 R15.16
N$22
  Bottom 0.305: R17.10 SV7.6
N$23  (via drill 0.6)
  Top 0.305: SJ4.1 36.83,14.61 v43.18,20.95
  Bottom 0.305: U1.3 37.72,26.42 v43.18,20.95 49.53,14.61 R9.2
N$24
  Bottom 0.305: U1.4 36.45,25.78 47.62,14.61 R10.2
N$25
  Bottom 0.305: U1.5 35.84,25.12 45.72,15.24 R11.2
N$26
  Bottom 0.305: U1.24 20.18,25.12 R12.2
N$29
  Bottom 0.305: R15.2 39.37,10.16 40.01,9.53 SV8.5
N$30
  Bottom 0.305: R15.1 40.64,10.16 SV8.6
N$31
  Top 0.305: 21.59,47.62 D9.A | 21.59,47.62 C2.2 | 21.59,47.62 19.05,47.62 D3.C
N$32
  Bottom 0.305: R15.4 36.83,11.43 34.92,9.53 SV2.5
N$33
  Bottom 0.305: SV3.6 32.38,9.53 33.02,10.16 34.29,10.16 35.56,11.43 R15.5
N$34
  Bottom 0.305: R15.6 34.29,11.43 33.66,10.79 31.11,10.79 29.84,9.53 SV3.5
N$35
  Bottom 0.305: U1.7 34.59,23.82 39.37,19.05 R15.15
N$36
  Bottom 0.305: U1.8 33.98,23.16 38.1,19.05 R15.14
N$38
  Bottom 0.305: U1.9 33.35,22.53 36.83,19.05 R15.13
N$39
  Bottom 0.305: U1.10 32.74,21.87 35.56,19.05 R15.12
N$40
  Bottom 0.305: U1.11 32.13,21.21 34.29,19.05 R15.11
N$41
  Bottom 0.305: U1.12 31.5,20.57 33.02,19.05 R15.10
N$42
  Bottom 0.305: 31.75,17.78 31.69,17.78 R15.9 31.75,19.05 30.89,19.91 U1.13
N$43
  Bottom 0.305: U1.15 21.82,19.28 20.95,18.41 R13.16
N$44
  Bottom 0.305: U1.16 21.18,19.91 19.68,18.41 R13.15
N$45
  Bottom 0.305: U1.17 20.57,20.57 18.41,18.41 R13.14
N$46
  Bottom 0.305: U1.18 19.94,21.21 17.14,18.41 R13.13
N$47
  Bottom 0.305: U1.19 19.33,21.87 15.88,18.41 R13.12
N$48
  Bottom 0.305: U1.20 18.72,22.53 14.61,18.41 R13.11
N$49
  Bottom 0.305: U1.21 18.09,23.16 13.34,18.41 R13.10
N$50
  Bottom 0.305: U1.22 17.48,23.82 12.06,18.41 R13.9
N$51
  Bottom 0.305: 32.38,14.61 29.84,14.61 27.94,12.7 10.16,12.7
  Bottom 0.406: R15.7 33.02,13.97 32.38,14.61 | SV5.20 10.16,12.7
N$52
  Bottom 0.406: SV5.18 5.71,6.35 10.79,11.43 30.54,11.43 R15.8
N$53
  Bottom 0.406: R13.8 12.01,9.46 SV5.16
N$54
  Bottom 0.406: R13.7 13.34,8.26 SV5.14
N$55
  Bottom 0.406: R13.6 14.61,6.99 SV5.12
N$56
  Bottom 0.406: SV5.10 R13.5
N$57
  Bottom 0.406: R13.4 17.14,6.99 SV5.8
N$58
  Bottom 0.406: R13.3 18.41,7.62 20.32,5.71 SV5.6
N$59
  Bottom 0.406: R13.2 19.68,7.62 20.32,6.99 22.23,6.99 SV5.4
N$60
  Bottom 0.406: R13.1 22.29,9.46 SV5.2
N$61
  Top 0.305: R14.2 C1.1
N$62  (via drill 0.6)
  Top 0.305: v46.99,24.13 43.18,24.13 34.92,15.88 29.84,15.88 29.84,17.78 26.67,17.78 26.04,18.41 U$1.3 21.59,18.41 20.95,17.78 20.54,17.78 R26.2
  Bottom 0.305: v46.99,24.13 JP4.1
N$63  (via drill 0.6)
  Top 0.305: R30.1 R4.2 38.52,49.53 37.47,49.53 36.2,48.26 v36.2,47.62 36.2,42.55 35.56,41.91 U$2.7 | LED1.A 35.15,25.62 37.47,27.94 37.47,35.56 v36.2,36.83
  Bottom 0.305: v36.2,36.83 v36.2,47.62
N$64
  Bottom 0.305: R17.11 69.22,46.35 70.48,47.62 SV7.5
N$65
  Bottom 0.305: R17.12 70.48,46.35 73.03,48.9 SV7.4
N$71
  Bottom 0.305: R17.13 71.75,46.35 SV7.3
N$72
  Bottom 0.305: SV7.2 75.56,47.62 74.3,47.62 73.03,46.35 R17.14
N$73
  Bottom 0.305: 74.3,45.09 R17.15 74.3,45.72 74.93,46.35 76.83,46.35 SV7.1
N$75
  Top 0.305: Q2.G 20.32,34.29 R16.2 20.54,20.95 U$1.1 22.68,22.68 25.4,25.4 32.8,25.4 LED2.A
N$78
  Top 0.305: SV6.1 79.38,23.5 75.56,19.68 R20.9
  Top 0.406: R20.9 74.93,19.68
N$79
  Top 0.305: U$1.2 20.54,19.68 R16.1 R24.2
N$80
  Top 0.305: R21.2 R30.2 40.85,48.26 44.45,48.26 C12.1
  Bottom 0.305: C12.1 50.8,47.62 51.44,48.26 51.44,49.53 52.07,50.16 JP5.1
N$82
  Bottom 0.305: R15.3 38.1,11.43 37.47,10.79 SV2.6
N$83
  Top 0.305: SV6.2 80.64,26.04 75.56,20.95
  Top 0.406: R20.10 75.56,20.95
N$85
  Bottom 0.305: R28.1 79.38,17.78 X3.3
N$92
  Top 0.305: SV6.3 78.11,28.57 78.11,25.4 74.93,22.23 R20.11
N$93
  Top 0.305: SV6.4 79.38,31.11 77.47,29.21 77.47,26.04 74.93,23.5 R20.12
N$94
  Top 0.305: SV6.5 80.64,33.66 76.83,29.84 76.83,26.67 74.93,24.77 R20.13
N$95
  Top 0.305: SV6.6 80.01,36.2 79.38,35.56 79.38,33.66 76.2,30.48 76.2,27.94 74.3,26.04 R20.14
N$96
  Top 0.305: SV6.7 79.38,38.73 78.74,38.1 78.74,34.29 75.56,31.11 75.56,28.57 74.3,27.3 R20.15
N$97
  Top 0.305: SV6.8 78.74,41.27 78.11,40.64 78.11,34.92 74.93,31.75 74.93,29.21 74.3,28.57 R20.16
N$98
  Top 0.305: R25.2 61.18,40.85 S1.3 S1.4
N$105
  Top 0.305: LED2.C R23.2
N$132
  Bottom 0.305: R27.1 X3.1
N$133
  Top 0.305: U$1.7 U$1.6
SCL  (via drill 0.6)
  Top 0.305: v61.59,31.75 v73.66,31.75 77.47,35.56 77.47,37.88 R19.1 | D8.P$6 55.26,31.73 v55.24,31.75 | v79.38,10.16 R32.1
  Bottom 0.305: U1.26 24.51,26.42 26.67,28.57 52.7,28.57 53.98,29.84 53.98,31.11 54.61,31.75 v55.24,31.75 v61.59,31.75 | v73.66,31.75 78.74,26.67 78.74,22.23 80.64,20.32 81.92,20.32 82.55,19.68 82.55,12.06 80.01,9.53 | 80.01,9.53 78.11,7.62 SV1.5 | 80.01,9.53 v79.38,10.16
SDA  (via drill 0.6)
  Top 0.305: 75.56,34.92 73.66,33.02 v61.59,33.02 61.58,33.03 D8.P$3 | 75.56,34.92 v76.52,35.88 | 75.56,34.92 R18.1 | R31.1 80.01,8.26 80.01,7.62 80.64,6.99 SV1.3
  Bottom 0.305: U1.27 23.9,27.08 26.04,29.21 52.07,29.21 53.34,30.48 53.34,31.75 54.61,33.02 v61.59,33.02 | 77.47,34.92 v76.52,35.88 80.01,32.38 80.01,22.23 80.64,21.59 82.55,21.59 83.82,20.32 83.82,11.43 80.64,8.26 SV1.3
~ENAB_PCA9685PW  (via drill 0.6)
  Top 0.305: SJ1.1 55.37,10.92 v54.61,10.16
  Bottom 0.305: R29.2 14.7,24.46 U1.23 23.8,24.46 24.13,24.13 24.13,16.51 24.77,15.88 41.27,15.88 42.55,14.61 42.55,12.06 44.45,10.16 44.45,8.89 45.72,7.62 50.16,7.62 52.7,10.16 v54.61,10.16

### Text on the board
Top: TOP | Robot PCB#1 | Alex Lee
Bottom: BOTTOM
tNames: Connect GPIO17 | #18 | #17 | GND | +5V | +3.3V | #25 | #24 | #23 | #22 | #21 | SDA | Power | to coil input | SCL | #4 | #7 | Coil | #8 | #9 | Coil | #10 | Connect GPIO4 | to coil output | #11 | GND | TXD | #14 | RXD | #15 | +5V | Raspberry Spy | +3.3V | Robot PCB | Licensed under CERN OHL v.1.1 | Bump Sensors | i2c Address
